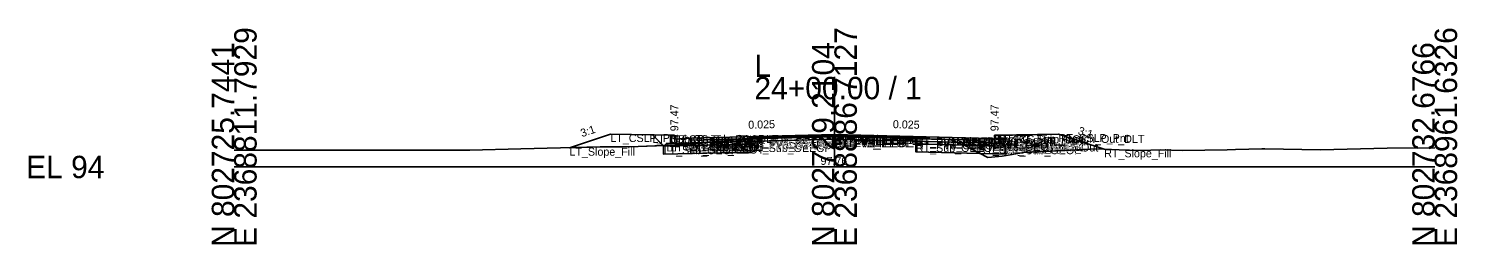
# Model space of a CAD drawing. Extents: x -26 to 8153, y -10 to 9520.
# Drawn here: x 974.3 to 1152.8, y 6490.3 to 6517.3 of the extents above; entities that cross this region are included whole.
import ezdxf

# ---------------------------------------------------------------- set-up
doc = ezdxf.new("R2010")
doc.units = 0
for name, color, linetype in [('Exist CMT Pavement', 7, 'Continuous'), ('Exist Cross Section Cell', 7, 'Continuous'), ('Exist XS Center Line Elevation Label', 7, 'Continuous'), ('Exist XS Ground Line', 7, 'Continuous'), ('Prop CMT Conc Surface', 7, 'Continuous'), ('Prop CMT Concrete Structures', 7, 'Continuous'), ('Prop CMT Pvmt Course 1', 7, 'Continuous'), ('Prop CMT Pvmt Course 1 CG', 7, 'Continuous'), ('Prop CMT Pvmt Course 1 Wedge', 7, 'Continuous'), ('Prop CMT Pvmt Course 2', 7, 'Continuous'), ('Prop CMT Pvmt Course 2 Wedge', 7, 'Continuous'), ('Prop CMT Pvmt Course 3', 7, 'Continuous'), ('Prop CMT Pvmt Course 3 Wedge', 7, 'Continuous'), ('Prop CMT Pvmt Surface', 7, 'Continuous'), ('Prop CMT Pvmt Wedge Surface 1', 7, 'Continuous'), ('Prop CMT Pvmt Wedge Surface 2', 7, 'Continuous'), ('Prop CMT Pvmt Wedge Surface 3', 7, 'Continuous'), ('Prop CMT Shallow Undercut', 7, 'Continuous'), ('Prop CMT Shallow Undercut Boundary', 7, 'Continuous'), ('Prop CMT Slope Grass', 7, 'Continuous'), ('Prop CMT Subgrade Earthwork', 7, 'Continuous'), ('Prop XS Earthwork Shape', 7, 'Continuous'), ('Prop XS Hydro Elevations', 7, 'Continuous'), ('Prop XS SE Text', 7, 'Continuous'), ('Prop XS Side Slope Text', 7, 'Continuous'), ('Prop XS Subgrade Earthwork', 7, 'Continuous'), ('Scratch_Level_2', 7, 'Continuous'), ('Scratch_Level_6', 7, 'Continuous')]:
    doc.layers.add(name, color=color, linetype=linetype)

msp = doc.modelspace()

# ---------------------------------------------------------------- linework, layer by layer
at = {"layer": 'Exist CMT Pavement'}
for p, q in [((1064.48, 6503.5), (1066.28, 6503.55)), ((1066.28, 6503.55), (1074.86, 6503.76)), ((1074.86, 6503.76), (1076.69, 6503.75)), ((1076.69, 6503.75), (1085.18, 6503.71))]:
    msp.add_line(p, q, dxfattribs=at)
at = {"layer": 'Exist Cross Section Cell'}
for p, q in [((1075, 6500), (1075, 6511.27)), ((1000, 6500), (1075, 6500)), ((1075, 6500), (1150, 6500))]:
    msp.add_line(p, q, dxfattribs=at)
at = {"layer": 'Exist XS Ground Line'}
for p, q in [((1029.44, 6502.12), (1035.8, 6502.27)), ((1035.8, 6502.27), (1045.74, 6502.5)), ((1045.74, 6502.5), (1048.46, 6502.54)), ((1048.46, 6502.54), (1050.46, 6502.58)), ((1050.46, 6502.58), (1055.06, 6502.72)), ((1055.06, 6502.72), (1058.19, 6503.03)), ((1058.19, 6503.03), (1061.73, 6503.33)), ((1061.73, 6503.33), (1064.48, 6503.5)), ((1064.48, 6503.5), (1066.28, 6503.55)), ((1066.28, 6503.55), (1074.86, 6503.76)), ((1074.86, 6503.76), (1076.69, 6503.75)), ((1076.69, 6503.75), (1085.18, 6503.71)), ((1085.18, 6503.71), (1086.55, 6503.52)), ((1086.55, 6503.52), (1089.44, 6503.45)), ((1089.44, 6503.45), (1091.2, 6502.73)), ((1091.2, 6502.73), (1094.15, 6501.17)), ((1098.68, 6501.81), (1107.73, 6502.25)), ((1107.73, 6502.25), (1112.44, 6502.06)), ((1124.06, 6502.13), (1125.11, 6502.2)), ((1125.11, 6502.2), (1126.79, 6502.22)), ((1126.79, 6502.22), (1128.41, 6502.27)), ((1128.41, 6502.27), (1128.77, 6502.28)), ((1128.77, 6502.28), (1135.72, 6502.13)), ((1135.72, 6502.13), (1144.06, 6502.35)), ((1144.06, 6502.35), (1150, 6502.39)), ((1000, 6502.1), (1004.14, 6502.1)), ((1004.14, 6502.1), (1015.4, 6502.12)), ((1015.4, 6502.12), (1029.44, 6502.12)), ((1094.15, 6501.17), (1095.97, 6501.36)), ((1095.97, 6501.36), (1098.68, 6501.81)), ((1112.44, 6502.06), (1114.53, 6502.11)), ((1114.53, 6502.11), (1115.71, 6502.13)), ((1115.71, 6502.13), (1118.49, 6502.07)), ((1118.49, 6502.07), (1124.06, 6502.13))]:
    msp.add_line(p, q, dxfattribs=at)
at = {"layer": 'Prop CMT Conc Surface'}
for points in [[(1055, 6503.47), (1055, 6503.97), (1054.5, 6503.97)], [(1095, 6503.47), (1095, 6503.97), (1095.5, 6503.97)], [(1057, 6503.6), (1055, 6503.47)], [(1093, 6503.6), (1095, 6503.47)]]:
    msp.add_lwpolyline(points, dxfattribs=at)
at = {"layer": 'Prop CMT Concrete Structures'}
for points in [[(1057, 6503.6), (1055, 6503.47), (1055, 6503.97), (1054.5, 6503.97)], [(1054.5, 6503.97), (1054.5, 6502.95), (1057, 6503.01)], [(1093, 6503.6), (1095, 6503.47), (1095, 6503.97), (1095.5, 6503.97)], [(1095.5, 6503.97), (1095.5, 6502.95), (1093, 6503.01)], [(1057, 6503.01), (1057, 6503.6)], [(1093, 6503.01), (1093, 6503.6)]]:
    msp.add_lwpolyline(points, dxfattribs=at)
at = {"layer": 'Prop CMT Pvmt Course 1'}
for points in [[(1075, 6504.05), (1057, 6503.6)], [(1075, 6503.8), (1075, 6504.05)], [(1075, 6504.05), (1093, 6503.6)], [(1075, 6503.8), (1075, 6504.05)], [(1057, 6503.6), (1057, 6503.35)], [(1057, 6503.35), (1064.48, 6503.53)], [(1064.48, 6503.66), (1075, 6503.92)], [(1064.48, 6503.53), (1064.48, 6503.66)], [(1075, 6503.92), (1075, 6503.8), (1075, 6503.8)], [(1085.18, 6503.67), (1075, 6503.92)], [(1075, 6503.92), (1075, 6503.8), (1075, 6503.8)], [(1085.18, 6503.54), (1085.18, 6503.67)], [(1093, 6503.35), (1085.18, 6503.54)], [(1093, 6503.6), (1093, 6503.35)]]:
    msp.add_lwpolyline(points, dxfattribs=at)
at = {"layer": 'Prop CMT Pvmt Course 1 CG'}
for points in [[(1057, 6503.01), (1054, 6502.94), (1053.66, 6502.6)], [(1053.66, 6502.6), (1057, 6502.68)], [(1057, 6502.68), (1057, 6503.01)], [(1093, 6503.01), (1096, 6502.94), (1096.34, 6502.6)], [(1093, 6502.68), (1093, 6503.01)], [(1096.34, 6502.6), (1093, 6502.68)]]:
    msp.add_lwpolyline(points, dxfattribs=at)
at = {"layer": 'Prop CMT Pvmt Course 1 Wedge'}
for points in [[(1075, 6503.92), (1064.48, 6503.66)], [(1075, 6503.92), (1085.18, 6503.67)]]:
    msp.add_lwpolyline(points, dxfattribs=at)
at = {"layer": 'Prop CMT Pvmt Course 2'}
for points in [[(1064.48, 6503.53), (1057, 6503.35)], [(1057, 6503.35), (1057, 6503.02)], [(1057, 6503.02), (1064.48, 6503.2)], [(1064.48, 6503.2), (1064.48, 6503.53)], [(1085.18, 6503.21), (1085.18, 6503.54)], [(1085.18, 6503.54), (1093, 6503.35)], [(1093, 6503.02), (1085.18, 6503.21)], [(1093, 6503.35), (1093, 6503.02)]]:
    msp.add_lwpolyline(points, dxfattribs=at)
at = {"layer": 'Prop CMT Pvmt Course 2 Wedge'}
for points in [[(1075, 6503.8), (1064.48, 6503.53)], [(1075, 6503.8), (1085.18, 6503.54)]]:
    msp.add_lwpolyline(points, dxfattribs=at)
at = {"layer": 'Prop CMT Pvmt Course 3'}
for points in [[(1064.48, 6503.2), (1057, 6503.02)], [(1057, 6503.02), (1057, 6502.68)], [(1057, 6502.68), (1064.48, 6502.87)], [(1064.48, 6502.87), (1064.48, 6503.2)], [(1085.18, 6503.21), (1093, 6503.02)], [(1085.18, 6502.88), (1085.18, 6503.21)], [(1093, 6502.68), (1085.18, 6502.88)], [(1093, 6503.02), (1093, 6502.68)]]:
    msp.add_lwpolyline(points, dxfattribs=at)
at = {"layer": 'Prop CMT Pvmt Course 3 Wedge'}
for points in [[(1075, 6503.47), (1064.48, 6503.2)], [(1075, 6503.47), (1085.18, 6503.21)]]:
    msp.add_lwpolyline(points, dxfattribs=at)
at = {"layer": 'Prop CMT Pvmt Surface'}
for points in [[(1075, 6504.05), (1057, 6503.6)], [(1075, 6504.05), (1093, 6503.6)]]:
    msp.add_lwpolyline(points, dxfattribs=at)
at = {"layer": 'Prop CMT Pvmt Wedge Surface 1'}
for points in [[(1057, 6503.35), (1057, 6503.6)], [(1064.48, 6503.53), (1057, 6503.35)], [(1075, 6503.92), (1064.48, 6503.66)], [(1064.48, 6503.66), (1064.48, 6503.53)], [(1075, 6503.92), (1085.18, 6503.67)], [(1085.18, 6503.67), (1085.18, 6503.54)], [(1085.18, 6503.54), (1093, 6503.35)], [(1093, 6503.35), (1093, 6503.6)]]:
    msp.add_lwpolyline(points, dxfattribs=at)
at = {"layer": 'Prop CMT Pvmt Wedge Surface 2'}
for points in [[(1075, 6503.8), (1057, 6503.35)], [(1057, 6503.35), (1057, 6503.6)], [(1075, 6503.8), (1093, 6503.35)], [(1093, 6503.35), (1093, 6503.6)]]:
    msp.add_lwpolyline(points, dxfattribs=at)
at = {"layer": 'Prop CMT Pvmt Wedge Surface 3'}
for points in [[(1057, 6503.02), (1057, 6503.6)], [(1075, 6503.47), (1057, 6503.02)], [(1075, 6503.47), (1093, 6503.02)], [(1093, 6503.02), (1093, 6503.6)]]:
    msp.add_lwpolyline(points, dxfattribs=at)
at = {"layer": 'Prop CMT Shallow Undercut'}
for p, q in [((1064.48, 6502.87), (1053.66, 6502.6)), ((1053.66, 6502.6), (1053.66, 6501.6)), ((1064.48, 6501.87), (1064.48, 6502.87)), ((1053.66, 6501.6), (1064.48, 6501.87))]:
    msp.add_line(p, q, dxfattribs=at)
msp.add_lwpolyline([(1093.19, 6501.68), (1085.18, 6501.88), (1085.18, 6502.88), (1091.2, 6502.73)], close=True, dxfattribs=at)
at = {"layer": 'Prop CMT Shallow Undercut Boundary'}
for p, q in [((1053.66, 6502.6), (1064.48, 6502.87)), ((1053.66, 6502.6), (1053.66, 6501.6)), ((1064.48, 6502.87), (1064.48, 6501.87)), ((1085.18, 6502.88), (1085.18, 6501.88)), ((1085.18, 6502.88), (1096.34, 6502.6)), ((1096.34, 6502.6), (1096.34, 6501.6)), ((1053.66, 6501.6), (1064.48, 6501.87)), ((1096.34, 6501.6), (1085.18, 6501.88))]:
    msp.add_line(p, q, dxfattribs=at)
at = {"layer": 'Prop CMT Slope Grass'}
for points in [[(1054.5, 6503.97), (1047, 6504.12), (1041.89, 6502.41)], [(1095.5, 6503.97), (1103, 6504.12), (1108.71, 6502.21)]]:
    msp.add_lwpolyline(points, dxfattribs=at)
at = {"layer": 'Prop CMT Subgrade Earthwork'}
for points in [[(1057, 6502.68), (1053.66, 6502.6), (1052.25, 6504.01)], [(1093, 6502.68), (1096.34, 6502.6), (1097.75, 6504.01)], [(1064.48, 6502.87), (1057, 6502.68)], [(1064.48, 6502.87), (1064.5, 6503.5)], [(1085.18, 6502.88), (1085.16, 6503.71)], [(1085.18, 6502.88), (1093, 6502.68)]]:
    msp.add_lwpolyline(points, dxfattribs=at)
at = {"layer": 'Prop XS Earthwork Shape'}
for points in [[(1047, 6504.12), (1041.89, 6502.41), (1045.74, 6502.5), (1048.46, 6502.54), (1050.46, 6502.58), (1053.59, 6502.67), (1052.25, 6504.01)], [(1095.97, 6501.36), (1098.68, 6501.81), (1107.73, 6502.25), (1108.71, 6502.21), (1103, 6504.12), (1097.75, 6504.01), (1096.34, 6502.6), (1096.34, 6501.6), (1093.19, 6501.68), (1094.15, 6501.17)], [(1053.59, 6502.67), (1055.06, 6502.72), (1058.19, 6503.03), (1061.73, 6503.33), (1064.48, 6503.5), (1064.5, 6503.5), (1064.48, 6502.87), (1057, 6502.68), (1053.66, 6502.6)], [(1064.48, 6502.87), (1064.48, 6501.87), (1053.66, 6501.6), (1053.66, 6502.6), (1057, 6502.68)], [(1085.18, 6502.88), (1085.16, 6503.71), (1085.18, 6503.71), (1086.55, 6503.52), (1089.44, 6503.45), (1091.2, 6502.73)], [(1091.2, 6502.73), (1093.19, 6501.68), (1085.18, 6501.88), (1085.18, 6502.88)], [(1091.2, 6502.73), (1093.19, 6501.68), (1096.34, 6501.6), (1096.34, 6502.6), (1093, 6502.68)]]:
    msp.add_lwpolyline(points, close=True, dxfattribs=at)
at = {"layer": 'Prop XS Subgrade Earthwork'}
for p, q in [((1064.48, 6502.87), (1053.66, 6502.6)), ((1085.18, 6502.88), (1096.34, 6502.6))]:
    msp.add_line(p, q, dxfattribs=at)
at = {"layer": 'Scratch_Level_6'}
for p, q in [((1064.48, 6502.87), (1053.66, 6502.6)), ((1053.66, 6502.6), (1053.66, 6501.6)), ((1064.48, 6501.87), (1064.48, 6502.87)), ((1053.66, 6501.6), (1064.48, 6501.87))]:
    msp.add_line(p, q, dxfattribs=at)
msp.add_lwpolyline([(1093.19, 6501.68), (1085.18, 6501.88), (1085.18, 6502.88), (1091.2, 6502.73)], close=True, dxfattribs=at)

# ---------------------------------------------------------------- texts
at = {"layer": 'Exist Cross Section Cell'}
for s, p in [('E 2368811.7929', (1002.8, 6490)), ('E 2368886.7127', (1077.8, 6490)), ('E 2368961.6326', (1152.8, 6490)), ('N 802725.7441', (1000, 6490)), ('N 802729.2104', (1075, 6490)), ('N 802732.6766', (1150, 6490))]:
    msp.add_text(s, height=2.8, rotation=90, dxfattribs=at).set_placement(p)
for s, p in [('L', (1065, 6511.27)), ('24+00.00 / 1', (1065, 6508.47)), ('EL 94', (974, 6498.6))]:
    msp.add_text(s, height=2.8, dxfattribs=at).set_placement(p)
at = {"layer": 'Exist XS Center Line Elevation Label'}
msp.add_text('97.76', height=1, dxfattribs=at).set_placement((1073.26, 6500.26))
at = {"layer": 'Prop XS Hydro Elevations'}
for p in [(1055.5, 6504.47), (1095.5, 6504.47)]:
    msp.add_text('97.47', height=1, rotation=90, dxfattribs=at).set_placement(p)
at = {"layer": 'Prop XS SE Text'}
for rotation, p in [(1.4321, (1064.24, 6504.78)), (358.5679, (1082.29, 6504.86))]:
    msp.add_text('0.025', height=1, rotation=rotation, dxfattribs=at).set_placement(p)
at = {"layer": 'Prop XS Side Slope Text'}
for rotation, p in [(18.4349, (1043.46, 6503.72)), (341.5651, (1105.34, 6504.13))]:
    msp.add_text('3:1', height=1, rotation=rotation, dxfattribs=at).set_placement(p)
at = {"layer": 'Scratch_Level_2'}
for s, p in [('LT_CSLP_Pnt', (1047, 6503.12)), ('LT_Sub_Trench_Out_DLT', (1052.25, 6503.01)), ('LT_CG_Top_BOC', (1054.5, 6502.97)), ('LT_CG_Top_Face', (1055, 6502.97)), ('PV1_PGL', (1075, 6503.05)), ('RT_CG_Top_Face', (1095, 6502.97)), ('RT_CG_Top_BOC', (1095.5, 6502.97)), ('RT_Sub_Trench_Out_DLT', (1097.75, 6503.01)), ('RT_CSLP_Pnt', (1103, 6503.12)), ('LT_Slope_Fill', (1041.89, 6501.41)), ('LT_Sub_OEOP', (1053.66, 6501.6)), ('LT_CG1_Shelf_Out', (1054, 6501.94)), ('LT_CG_Bot_BOC', (1054.5, 6501.95)), ('LT_CG_Top_Gut', (1055, 6502.47)), ('LT_PV1_OEOT', (1057, 6502.6)), ('LT_PV2_OEOT', (1057, 6502.35)), ('LT_PV3_OEOT', (1057, 6502.02)), ('LT_CG_Bot_IE', (1057, 6502.01)), ('LT_Sub_OEOT', (1057, 6501.68)), ('LT_PV1_OEEOP', (1064.48, 6502.66)), ('LT_PV2_OEEOP', (1064.48, 6502.53)), ('LT_PV_OEEOP_EG', (1064.48, 6502.5)), ('LT_PV3_OEEOP', (1064.48, 6502.2)), ('LT_Sub_OEEOP', (1064.48, 6501.87)), ('LT_PV_Sub_Tie_Out', (1064.5, 6502.5)), ('RT_PV1_IEEOP', (1075, 6502.92)), ('LT_PV1_IEEOP', (1075, 6502.92)), ('RT_PV2_IEEOP', (1075, 6502.8)), ('LT_PV2_IEEOP', (1075, 6502.8)), ('PV2_PGL', (1075, 6502.8)), ('RT_PV_IEEOP_EG', (1075, 6502.76)), ('LT_PV_IEEOP_EG', (1075, 6502.76)), ('RT_PV3_IEEOP', (1075, 6502.47)), ('LT_PV3_IEEOP', (1075, 6502.47)), ('RT_PV_Sub_Tie_Out', (1085.16, 6502.71)), ('RT_PV_OEEOP_EG', (1085.18, 6502.71)), ('RT_PV1_OEEOP', (1085.18, 6502.67)), ('RT_PV2_OEEOP', (1085.18, 6502.54)), ('RT_PV3_OEEOP', (1085.18, 6502.21)), ('RT_Sub_OEEOP', (1085.18, 6501.88)), ('RT_PV1_OEOT', (1093, 6502.6)), ('RT_PV2_OEOT', (1093, 6502.35)), ('RT_PV3_OEOT', (1093, 6502.02)), ('RT_CG_Bot_IE', (1093, 6502.01)), ('RT_Sub_OEOT', (1093, 6501.68)), ('RT_CG_Top_Gut', (1095, 6502.47)), ('RT_CG_Bot_BOC', (1095.5, 6501.95)), ('RT_CG1_Shelf_Out', (1096, 6501.94)), ('RT_Sub_OEOP', (1096.34, 6501.6)), ('RT_Slope_Fill', (1108.71, 6501.21))]:
    msp.add_text(s, height=1, dxfattribs=at).set_placement(p)

doc.saveas('drawing.dxf')
